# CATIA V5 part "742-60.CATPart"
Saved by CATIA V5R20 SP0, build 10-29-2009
Part number: 742-60
Bounding box of the stored display mesh (mm): x -47.5 to 48, y -47.5 to 47.5, z -60 to 90
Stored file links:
  C:\Users\Utente\Desktop\IO LAVORO\3D X SITO CF\X SITO\742\742-60.CATPart
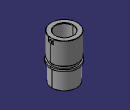
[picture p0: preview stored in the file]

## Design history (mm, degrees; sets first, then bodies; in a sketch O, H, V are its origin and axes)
Set1
  DatumSurface1 to DatumSurface38 "742-60"
Body1 (main body)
